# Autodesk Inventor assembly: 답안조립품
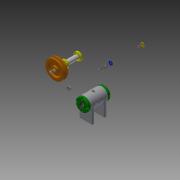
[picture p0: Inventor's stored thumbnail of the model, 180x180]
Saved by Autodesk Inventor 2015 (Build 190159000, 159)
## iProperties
Created: 2020-07
Part Number: 답안조립품
Document SubType Name: Assembly
Designer: 1015698
Author: 1015698
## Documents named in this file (15)
- C:\Users\1015698\Desktop\700706V1033\답안조립품.iam
- C:\Users\1015698\Desktop\700706V1033\본체.ipt
- C:\Users\1015698\Desktop\700706V1033\V벨트풀리.ipt
- C:\Users\1015698\Desktop\700706V1033\너트 M8.ipt
- C:\Users\1015698\Desktop\700706V1033\뒤커버.ipt
- C:\Users\1015698\Desktop\700706V1033\베어링 6002.ipt
- C:\Users\1015698\Desktop\700706V1033\볼트 M4x12.ipt
- C:\Users\1015698\Desktop\700706V1033\볼트 M6x8.ipt
- C:\Users\1015698\Desktop\700706V1033\스프링와셔 8.ipt
- C:\Users\1015698\Desktop\700706V1033\앞커버.ipt
- C:\Users\1015698\Desktop\700706V1033\오일 실 15 25 7.ipt
- C:\Users\1015698\Desktop\700706V1033\와셔 6x11.5.ipt
- C:\Users\1015698\Desktop\700706V1033\와셔 8x17.ipt
- C:\Users\1015698\Desktop\700706V1033\축.ipt
- C:\Users\1015698\Desktop\700706V1033\키 3x3x12.ipt
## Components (1 placed, 1 different names)
1. V벨트풀리:1
